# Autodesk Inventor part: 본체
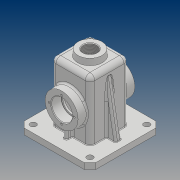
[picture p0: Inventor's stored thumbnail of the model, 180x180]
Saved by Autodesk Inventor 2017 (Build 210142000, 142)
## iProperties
Part Number: 본체
Material: 일반
Document SubType Name: Modeling
Designer: 20
Density: 1 g/cm^3
Appearance: 기본값
Author: 20
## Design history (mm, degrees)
sketch "스케치2"
  geometry: L1 (-32.5, -32.5)-(32.5, -32.5); L2 (32.5, -32.5)-(32.5, 32.5); L3 (32.5, 32.5)-(-32.5, 32.5); L4 (-32.5, 32.5)-(-32.5, -32.5); L5 (-32.5, -32.5)-(32.5, 32.5); L6 (32.5, -32.5)-(-32.5, 32.5); 1 further point
  constraints: 12 end point, 2 midpoint, 2 parallel, 1 horizontal, 1 perpendicular
  dimensions: "d2" = 65 distance of L2.end L3.end; "d3" = 65 distance of L1.end L2.end
extrude "돌출1" new body sketch "스케치2" distance "d4" = 110; taper "d5" = 0 deg
feature "쉘1" dims "d8" = 5
sketch "스케치3"
  geometry: L1 (60, -60)-(-60, -60); L2 (-60, -60)-(-60, 60); L3 (-60, 60)-(60, 60); L4 (60, 60)-(60, -60); L5 (60, -60)-(-60, 60); L6 (-60, -60)-(60, 60); L7 (-32.5, -32.5)-(-32.5, 32.5) reference; L8 (32.5, -32.5)-(-32.5, -32.5) reference; L9 (32.5, 32.5)-(32.5, -32.5) reference; L10 (-32.5, 32.5)-(32.5, 32.5) reference; A1 r 8 centre (-24.5, -24.5) between (-32.5, -24.5) and (-24.5, -32.5) reference; A2 r 8 centre (24.5, -24.5) between (24.5, -32.5) and (32.5, -24.5) reference; A3 r 8 centre (24.5, 24.5) between (32.5, 24.5) and (24.5, 32.5) reference; A4 r 8 centre (-24.5, 24.5) between (-24.5, 32.5) and (-32.5, 24.5) reference; 1 further point
  constraints: 12 end point, 2 midpoint, 2 parallel, 1 horizontal, 1 perpendicular
  dimensions: "d9" = 120 distance of L1.end L2.end; "d10" = 120 distance of L2.end L3.end
extrude "돌출2" join sketch "스케치3" distance "d11" = 10; taper "d12" = 0 deg
chamfer "모따기1" distance "d13" = 10; stored, may be unused: second distance "d14" = 2, angle "d15" = 45 deg
sketch "스케치10"
  geometry: L1 (-48, 10)-(-41.988, 44.095); L2 (50, 10)-(-50, 10) reference; L3 (-60, 0)-(-60, 10) reference; 1 further point
  constraints: 2 end point, 1 point on line
  dimensions: "d37" = 10 deg angle of L3 L1; "d38" = 12 distance from line of L3 L1.start; "d39" = 34.095 vertical distance of L1.start L1.end
feature "리브1" sketch "스케치10" dims "d40" = 1, "d41" = 10, "d42" = 0, "d43" = 0, "d44" = 1, "d45" = 1
sketch "스케치13"
  geometry: C1 r 20 at (0, 0); 1 further point
  constraints: 1 centre point, 1 coincident
  dimensions: "d57" = 40 diameter of C1
extrude "돌출9" join sketch "스케치13" distance "d58" = 10; taper "d59" = 0 deg
sketch "스케치14"
  geometry: 2 further points
  constraints: 1 coincident
hole "구멍1" sketch "스케치14" at (0, 0) diameter "d60" = 22.835; stored, may be unused: countersink angle "d64" = 90 deg, drill point angle "d66" = 118 deg; dims "d61" = 50, "d62" = 4, "d63" = 2, "d65" = 59.3
feature "면 기울기1" dims angle "d67" = 5 deg
fillet "모깎기4" dims "d91" = 8
fillet "모깎기5" dims "d92" = 3
fillet "모깎기6" dims "d93" = 3
fillet "모깎기7" dims "d94" = 3
sketch "스케치18"
  geometry: L1 (-17.5, -10)-(82.5, -10) reference; C1 r 27.5 at (32.5, 45); 2 further points
  constraints: 1 centre point, 1 midpoint, 1 vertical alignment
  dimensions: "d97" = 55 diameter of C1; "d98" = 55 distance from line of L1 C1.centre
extrude "돌출10" join sketch "스케치18" distance "d99" = 15; taper "d100" = 0 deg
sketch "스케치19"
  geometry: C1 r 15 at (0, 0); C2 r 27.5 at (0, 0) reference; 1 further point
  constraints: 1 centre point, 1 concentric
  dimensions: "d101" = 30 diameter of C1
extrude "돌출11" cut sketch "스케치19" stored distance "d102" = 15; taper "d103" = 0 deg
sketch "스케치20"
  geometry: C1 r 17.5 at (0, 0); C2 r 27.5 at (0, 0) reference; 1 further point
  constraints: 1 centre point, 1 concentric
  dimensions: "d104" = 35 diameter of C1
extrude "돌출12" cut sketch "스케치20" distance "d105" = 17; taper "d106" = 0 deg
sketch "스케치21" dims "d107" = 42
  geometry: C1 r 27.5 at (0, 0) reference; 3 further points
  constraints: 2 vertical alignment, 3 other
hole "구멍4" sketch "스케치21" at (0, 21) diameter "d108" = 3.242; stored, may be unused: countersink angle "d112" = 90 deg, drill point angle "d114" = 118 deg; dims "d109" = 8, "d110" = 4, "d111" = 2, "d113" = 10
sketch "스케치22"
  geometry: L1 (-42.5, 10)-(-42.5, 23.754); L2 (50, 10)-(-50, 10) reference; L3 (-27.5, 102)-(-27.5, 0) reference; 1 further point
  constraints: 2 end point, 1 point on line
  dimensions: "d119" = 15 distance between parallel lines of L3 L1; "d122" = 13.7535 distance of L1.start L1.end; "d123" = 90 deg angle of L2 L1 (derived)
feature "리브3" sketch "스케치22" dims "d124" = 1, "d125" = 6, "d126" = 0, "d127" = 0, "d128" = 1, "d129" = 1
fillet "모깎기8" dims "d130" = 8
fillet "모깎기15" dims "d137" = 3
fillet "모깎기16" dims "d138" = 3
fillet "모깎기17" dims "d139" = 3
fillet "모깎기21" dims "d143" = 3
fillet "모깎기22" dims "d144" = 3
fillet "모깎기23" dims "d145" = 3
fillet "모깎기24" dims "d146" = 1
chamfer "모따기2" distance "d147" = 1; stored, may be unused: second distance "d148" = 2, angle "d149" = 45 deg
sketch "스케치23"
  geometry: C1 r 5 at (-47.5, -47.5); 1 further point
  constraints: 1 centre point
  dimensions: "d150" = 10 diameter of C1; "d151" = 47.5 horizontal distance of C1.centre point (0, 0); "d152" = 47.5 horizontal distance of point (0, 0) C1.centre
extrude "돌출13" cut sketch "스케치23" distance "d153" = 10; taper "d154" = 0 deg
chamfer "모따기3" distance "d161" = 1; stored, may be unused: second distance "d162" = 2, angle "d163" = 45 deg
node "작업 평면1"
sketch "스케치26"
  geometry: L1 (-20, -65)-(20, -65) reference; L2 (32.5, -47)-(32.5, 44) reference; 2 further points
  constraints: 1 other
  dimensions: "d165" = 26 distance from line of L1 point (0, -39); "d166" = 32.5 distance from line of L2 point (0, -39)
feature "엠보싱1" sketch "스케치26" dims "d167" = 0.5, "d168" = 0
fillet "모깎기25" dims "d169" = 3
fillet "모깎기26" dims "d170" = 0.3
sketch "스케치27"
  geometry: 1 further point
node "솔리드1"
mirror "미러1"
pattern_circular "원형 패턴3" dims angle "d116" = 360 deg
mirror "미러3"
mirror "미러4"
pattern_linear "직사각형 패턴1" dims "d157" = 95, "d160" = 95
other parameters: "d164" = 44
